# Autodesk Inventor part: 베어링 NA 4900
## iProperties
Created: 2014-07
Part Number: 베어링 NA 4900
Material: Steel, Mild
Description: 니들 롤러 베어링 - 경계 치수 및 공차
Document SubType Name: Modeling
Standard: KS B 2029
Designer: KYOUNG IL JANG
Standards Organization: KS
Language: ko-KR
Size Designation: NA 4900 - 10 x 22 x 13
Categories: <MemberInstance><Categories><Category DisplayName="샤프트 부품" InternalName="7f7aeb1f-a693-4053-b835-cee3144e0d98" Mnemonic="SHFT"><Category DisplayName="베어링" Inter
Density: 1 g/cm^3
Company: 한국ATC센터
IsCustomPart: 0
Author: KYOUNG IL JANG
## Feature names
1. IDS_ARRAYROLLER[SIMPL:T] [Circular Pattern]
